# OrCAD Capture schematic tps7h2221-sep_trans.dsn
size A; title: TPS7H2221-SEP Radiation Tolerant; rev: *; note: Datasheet: SLVSGP1    EVM User Guide: SLVUCF4; note: 5.5-V, 1.25-A, 115-mOhm Load Switch
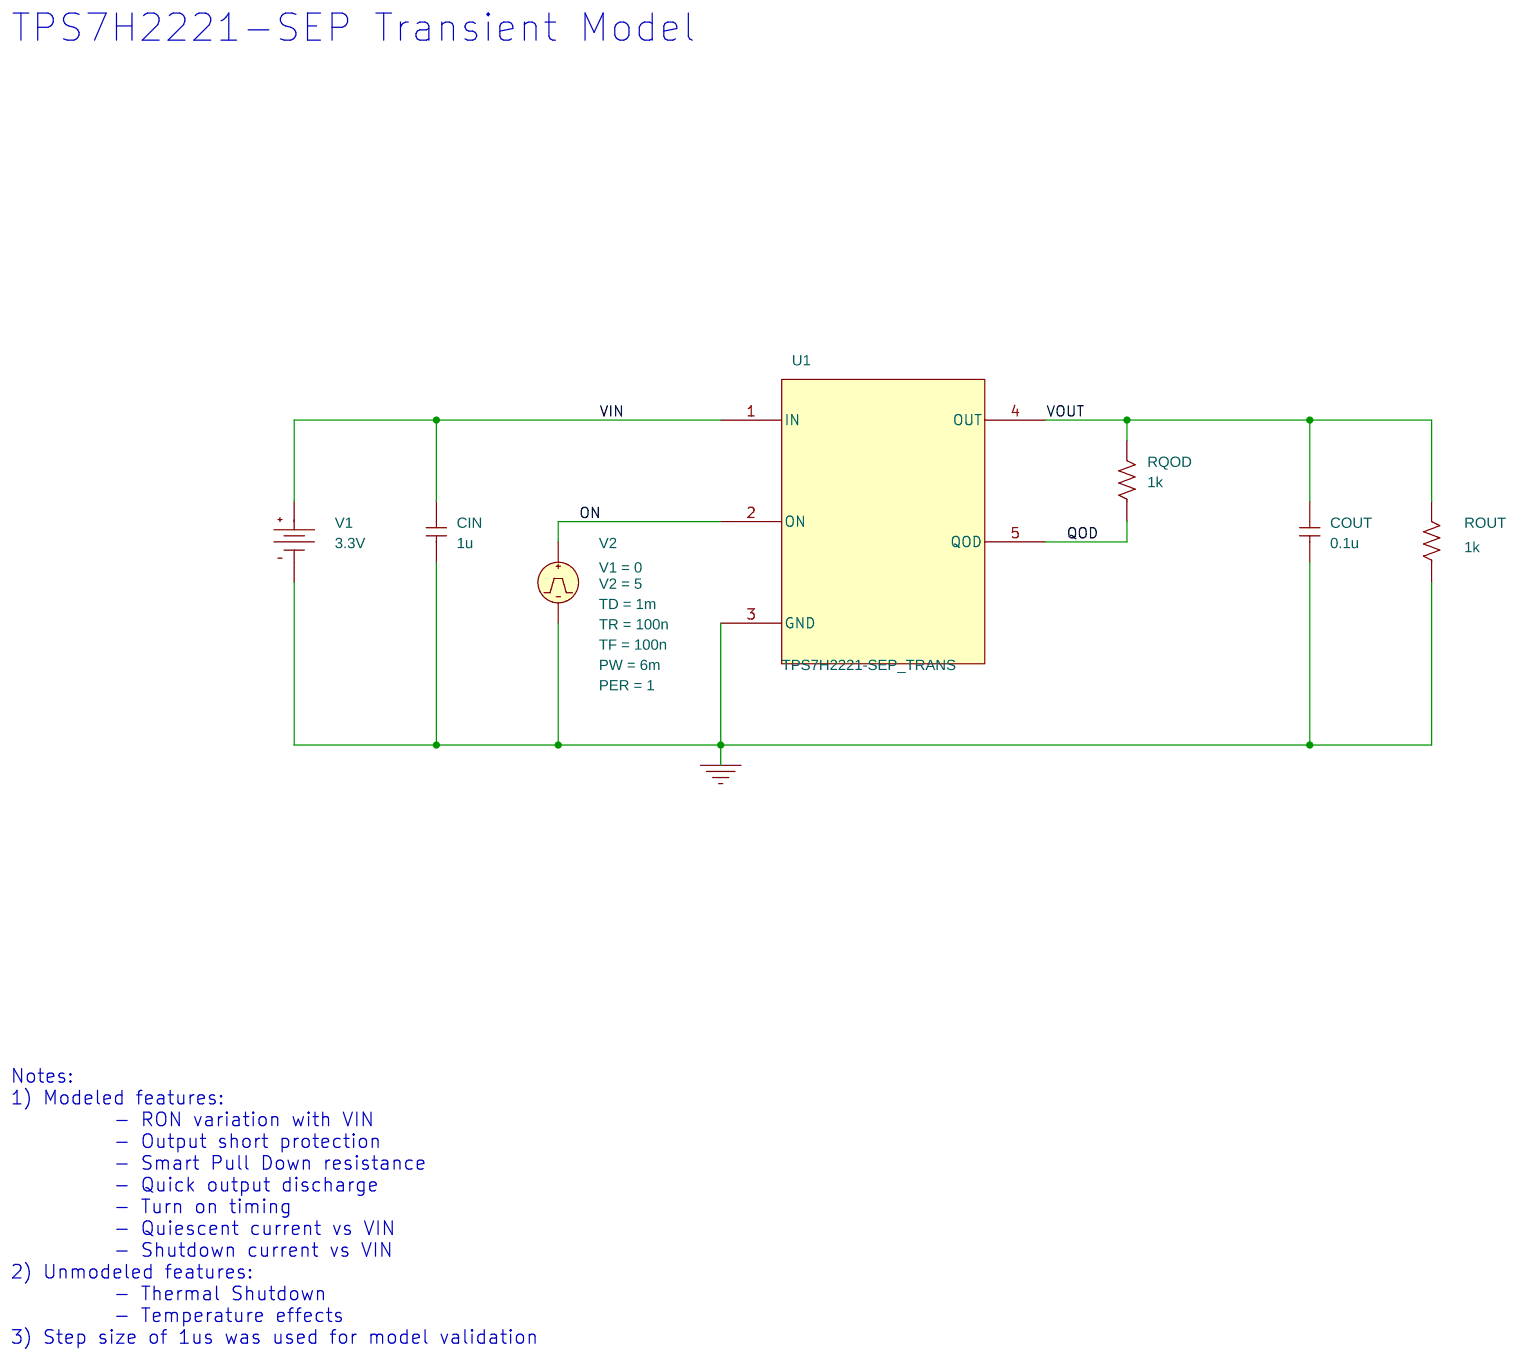
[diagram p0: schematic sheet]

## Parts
CIN  1u  [RAD/CK05]
COUT  0.1u  [RAD/CK05]
ROUT  1k  [AXRC05]
RQOD  1k  [AXRC05]
U1  TPS7H2221-SEP_TRANS
V1  VDC
V2  VPULSE

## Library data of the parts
CIN COUT = C: IC: 0
ROUT RQOD = R
U1 = TPS7H2221-SEP_TRANS_2
V1 = VDC: DC: 3.3V
V2 = VPULSE: PER: 1; PW: 6m; TD: 1m; TF: 100n; TR: 100n; V1: 0; V2: 5

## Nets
VIN: CIN.2 U1.1(IN) V1.0(+)
0: CIN.1 COUT.1 ROUT.1 U1.3(GND) V1.1(-) V2.2(-)
ON: U1.2(ON) V2.1(+)
QOD: RQOD.1 U1.5(QOD)
VOUT: COUT.2 ROUT.2 RQOD.2 U1.4(OUT)

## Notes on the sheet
- TPS7H2221-SEP Transient Model
- Notes:
  1) Modeled features:
            - RON variation with VIN
            - Output short protection
            - Smart Pull Down resistance
            - Quick output discharge
            - Turn on timing
            - Quiescent current vs VIN
            - Shutdown current vs VIN
  2) Unmodeled features:
            - Thermal Shutdown
            - Temperature effects
  3) Step size of 1us was used for model validation
